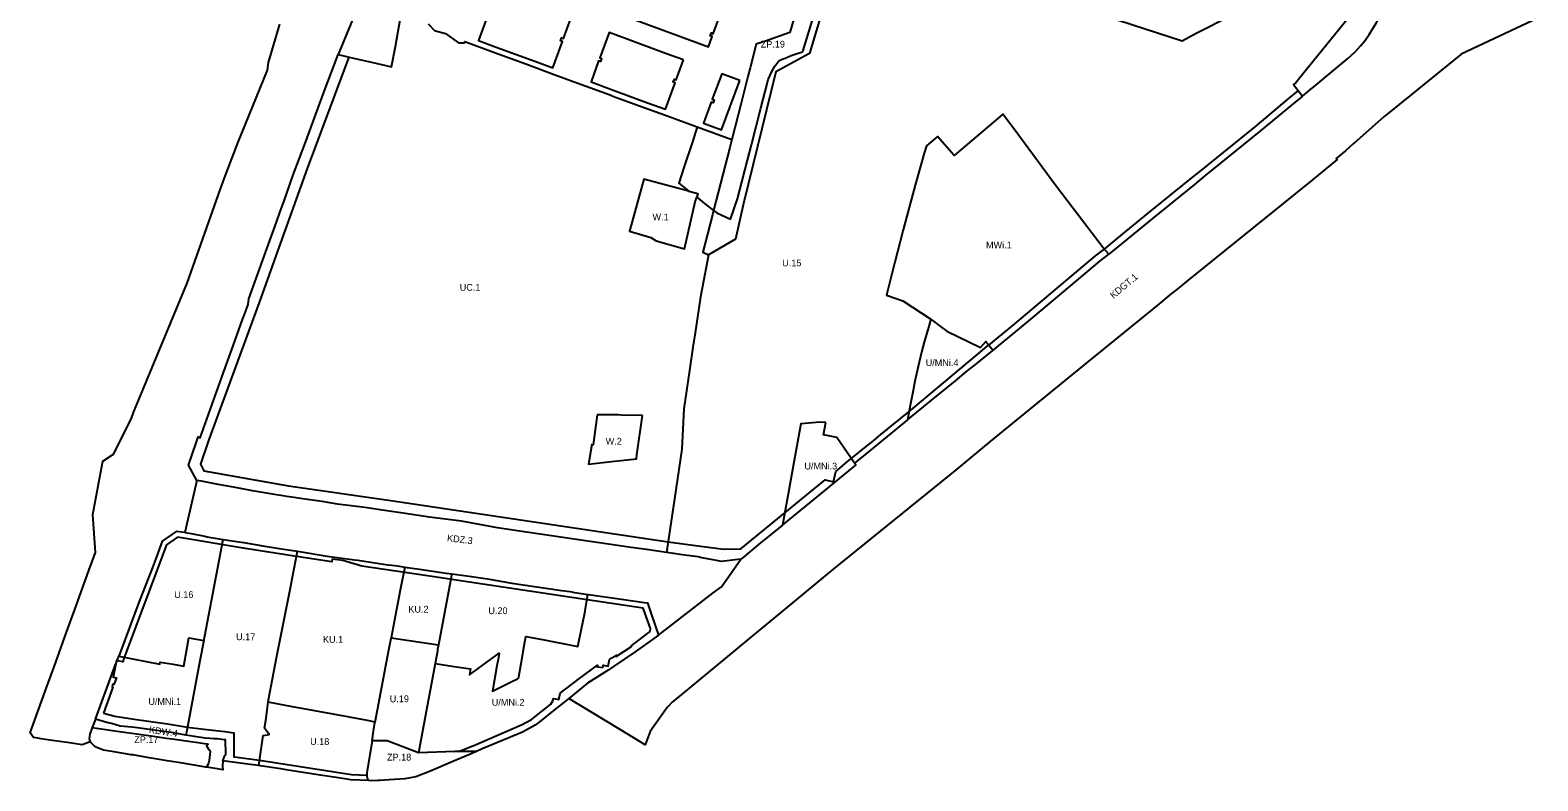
# Model space of a CAD drawing. Extents: x 7428689 to 7430424, y 5549101 to 5550539.
# Drawn here: x 7429291 to 7430402, y 5549101 to 5549654 of the extents above; entities that cross this region are included whole.
import ezdxf

# ---------------------------------------------------------------- set-up
doc = ezdxf.new("R2010")
doc.units = 0
for name, color, linetype in [('linie rozgraniczające', 7, 'Continuous'), ('nieprzekraczalne linie zabudowy', 7, 'Continuous'), ('obowiazujace linie zabudowy', 7, 'Continuous'), ('przeznaczenia terenów', 7, 'Continuous')]:
    doc.layers.add(name, color=color, linetype=linetype)

msp = doc.modelspace()

# ---------------------------------------------------------------- linework, layer by layer
at = {"layer": 'linie rozgraniczające'}
for points in [[(7430228.8, 5549605.5), (7430233.5, 5549609.5), (7430238.8, 5549613.8), (7430249.4, 5549622.6), (7430262.2, 5549633.2), (7430267.9, 5549638.5), (7430271.7, 5549642.7), (7430274.9, 5549646.3), (7430278.1, 5549651.1), (7430283.2, 5549659.4), (7430306.2, 5549703.6), (7430310, 5549710.9), (7430318.2, 5549726.4), (7430322.5, 5549734.6), (7430323, 5549735.8), (7430324.7, 5549739.9), (7430326.1, 5549745.2), (7430327.1, 5549750.3), (7430327.2, 5549753.5), (7430326.6, 5549756.8), (7430324.7, 5549761.7), (7430322.9, 5549765.9), (7430319.8, 5549769.8)], [(7429568.6, 5549761.1), (7429566.9, 5549757.4), (7429563.8, 5549750.5), (7429557, 5549735.5), (7429550.5, 5549716.1), (7429548.8, 5549710.9), (7429543.4, 5549697.4), (7429542.4, 5549694.9), (7429541.4, 5549692.4), (7429533.8, 5549674.3), (7429517.9, 5549636.2)], [(7429874.9, 5549734.7), (7429871, 5549721.6), (7429867.1, 5549708.1), (7429860.8, 5549686.4), (7429850.9, 5549652.5), (7429833, 5549646.2), (7429826.1, 5549643.8), (7429821.7, 5549626.5), (7429820.1, 5549620.2), (7429815, 5549600.4), (7429808.2, 5549573.6), (7429806.7, 5549567.7), (7429794.7, 5549521.4)], [(7429794.7, 5549521.4), (7429797.1, 5549519.5), (7429807.1, 5549514.9), (7429812.4, 5549529.9), (7429821.2, 5549564), (7429822.7, 5549569.8), (7429829.6, 5549596.7), (7429834.4, 5549615.7), (7429835, 5549617.8), (7429837.9, 5549624.3), (7429839.9, 5549627.8), (7429842.9, 5549631.6), (7429845.4, 5549632.8), (7429847.4, 5549633.7), (7429852, 5549635.5), (7429857.8, 5549637.4), (7429859.9, 5549638.1), (7429860.9, 5549639.3), (7429874.1, 5549682.9), (7429888.8, 5549731.4), (7429889.3, 5549732.8)], [(7430278.8, 5549683.1), (7430236.2, 5549630.6), (7430233.1, 5549626.7), (7430232.9, 5549626.4), (7430223.9, 5549615.4), (7430222.3, 5549614.1), (7430228.8, 5549605.5)], [(7429517.9, 5549636.2), (7429530.2, 5549633.4), (7429542.6, 5549630.6), (7429557.3, 5549627.3), (7429560.2, 5549642.3), (7429564, 5549663.2)], [(7430402.4, 5549663.1), (7430346, 5549636.5), (7430345.7, 5549636.3), (7430336.5, 5549628.9), (7430295, 5549595.3), (7430289.1, 5549590.5), (7430266.7, 5549570.7), (7430266.6, 5549570.7), (7430260.5, 5549565.4), (7430253.8, 5549559.6), (7430254.6, 5549558.8), (7430236.2, 5549544), (7430186.6, 5549503.9), (7430143.4, 5549469.1), (7430136.2, 5549463.2), (7430132.4, 5549460.2), (7430121.7, 5549451.4), (7430078.6, 5549416.3), (7430056.2, 5549398.1), (7429999, 5549351.4), (7429974, 5549330.6), (7429882.8, 5549257.1), (7429848.7, 5549228.9), (7429820.8, 5549205.8), (7429803.5, 5549191.5), (7429777.9, 5549170.4), (7429765.5, 5549160.1), (7429764.5, 5549159.3), (7429760.8, 5549155.3), (7429759.4, 5549153.3), (7429748.1, 5549137.3)], [(7429335, 5549129.9), (7429329.3, 5549127.6), (7429319.8, 5549129), (7429305.4, 5549131.1), (7429299, 5549132.1), (7429296.6, 5549132.4), (7429293.3, 5549132.9), (7429290.9, 5549136.3), (7429302.7, 5549169), (7429307.8, 5549183.1), (7429308.5, 5549185), (7429317.7, 5549210.5), (7429323.8, 5549227.2), (7429334.2, 5549256.1), (7429339, 5549269.2), (7429337, 5549297.4), (7429344.5, 5549336.6), (7429352.2, 5549341.7), (7429364.3, 5549365.5), (7429365.5, 5549368.3), (7429367.1, 5549372.4), (7429394.7, 5549438.7), (7429406.7, 5549467.7), (7429431.2, 5549537.2), (7429433.8, 5549544.7), (7429435.4, 5549548.7), (7429444.3, 5549571.6), (7429465.9, 5549624.8), (7429466.6, 5549630.4), (7429474.9, 5549658.6)], [(7429584.3, 5549658.9), (7429589.1, 5549654), (7429597.1, 5549651.7), (7429606.6, 5549644.9), (7429611, 5549644.9), (7429611.4, 5549645.8), (7429633.2, 5549637.8), (7429656.2, 5549629.4), (7429677.2, 5549621.6), (7429697.4, 5549614.2), (7429718.6, 5549606.5), (7429720.5, 5549605.7), (7429739.5, 5549598.8), (7429761.2, 5549590.8), (7429782.7, 5549582.9), (7429779.3, 5549572), (7429772.9, 5549553), (7429769.2, 5549541.5), (7429776.4, 5549535.6)], [(7429413.8, 5549322.4), (7429407.7, 5549333.6), (7429413.3, 5549350.1), (7429414.8, 5549354.5), (7429416.1, 5549353.9), (7429433.4, 5549401.9), (7429440.6, 5549421.7), (7429447.5, 5549440.9), (7429448.9, 5549444.8), (7429451.5, 5549452.1), (7429452.1, 5549456.3), (7429462.2, 5549484.3), (7429467.6, 5549499.2), (7429472.5, 5549512.7), (7429475.2, 5549520.5), (7429478, 5549527.7), (7429484.9, 5549547.5), (7429494.1, 5549572.3), (7429506.9, 5549607), (7429517.9, 5549636.2)], [(7430228.8, 5549605.5), (7430228.6, 5549605.4), (7430222.4, 5549600.3), (7430197, 5549579.2), (7430157.2, 5549547.1), (7430149.3, 5549540.6), (7430118.3, 5549515.5), (7430099.4, 5549500), (7430086.2, 5549489.1)], [(7430086.2, 5549489.1), (7430081.9, 5549493.9), (7430059.1, 5549523.7), (7430047.2, 5549539.3), (7430016.3, 5549581.3), (7430008.1, 5549592.4), (7430001.3, 5549586.6), (7429972, 5549561.8), (7429959.9, 5549575.9), (7429958.1, 5549574.3), (7429951.7, 5549569), (7429950, 5549563.5), (7429943.3, 5549539.9), (7429934.6, 5549507), (7429926.1, 5549474.6), (7429922.2, 5549458.9), (7429934.2, 5549454.7), (7429955, 5549441.2)], [(7429776.4, 5549535.6), (7429763.5, 5549539.1), (7429743.3, 5549544.5), (7429732.8, 5549506), (7429748.5, 5549501.4), (7429752.4, 5549499), (7429773.4, 5549493), (7429781.1, 5549527.6), (7429782.3, 5549531.2)], [(7429776.4, 5549535.6), (7429783.1, 5549533.8), (7429782.3, 5549531.2)], [(7429782.3, 5549531.2), (7429788.1, 5549526.6), (7429794.7, 5549521.4)], [(7429794.7, 5549521.4), (7429793.9, 5549518.1), (7429786.8, 5549490.6), (7429791.1, 5549488.6), (7429791.1, 5549488.6), (7429790.6, 5549485.9), (7429785.1, 5549457.8), (7429784.8, 5549455.9), (7429781.1, 5549431.1), (7429779.5, 5549420.5), (7429776.9, 5549403.5), (7429772.7, 5549375.2), (7429771.4, 5549345.5), (7429765.9, 5549308.9), (7429760, 5549269.3)], [(7430000.6, 5549418.2), (7430020.1, 5549434.1), (7430030.1, 5549442.4), (7430057.6, 5549465.6), (7430079.5, 5549484), (7430085.9, 5549488.9), (7430086.2, 5549489.1)], [(7429955, 5549441.2), (7429953.2, 5549435.2), (7429950.1, 5549424.4), (7429948, 5549416.9), (7429945.6, 5549406.3), (7429943.2, 5549395.6), (7429941.8, 5549388.7), (7429939.7, 5549377.7), (7429937.6, 5549367)], [(7429955, 5549441.2), (7429962.1, 5549435.9), (7429966.8, 5549432.5), (7429991.5, 5549420.4), (7429995.5, 5549424.7), (7430000.4, 5549418.8), (7430000.6, 5549418.2)], [(7429937.6, 5549367), (7429955.2, 5549381.3), (7429973, 5549395.8), (7429981.3, 5549402.6), (7429987.7, 5549407.7), (7430000.6, 5549418.2)], [(7429709, 5549370.8), (7429705.9, 5549348.7), (7429704.9, 5549349), (7429702.4, 5549334.4), (7429719.4, 5549336.3), (7429737.8, 5549338.4), (7429738.2, 5549341.3), (7429742.3, 5549370.3)], [(7429742.3, 5549370.3), (7429726.9, 5549370.5), (7429724.4, 5549370.8), (7429709, 5549370.8)], [(7429877.4, 5549365.2), (7429873.4, 5549365.3), (7429859.1, 5549364.1), (7429859.1, 5549364.1), (7429854.2, 5549337.2), (7429849.5, 5549311), (7429845.6, 5549289.5)], [(7429898.6, 5549335.2), (7429891, 5549346.1), (7429885.5, 5549354), (7429875.7, 5549355.9), (7429877.4, 5549365.2)], [(7429937.6, 5549367), (7429907.7, 5549342.6), (7429900, 5549336.3), (7429898.6, 5549335.2)], [(7429845.6, 5549289.5), (7429876.5, 5549314.7), (7429897.2, 5549331.6), (7429899.7, 5549333.6), (7429898.6, 5549335.2)], [(7429413.8, 5549322.4), (7429404.8, 5549284.1)], [(7429760, 5549269.3), (7429750.3, 5549270.7), (7429745.6, 5549271.4), (7429745.2, 5549271.4), (7429733.9, 5549273.1), (7429708.9, 5549276.7), (7429688.6, 5549279.7), (7429670.3, 5549282.3), (7429653.4, 5549284.9), (7429635.5, 5549287.6), (7429608.9, 5549292.4), (7429585.2, 5549295.4), (7429564.1, 5549298.5), (7429555.6, 5549299.8), (7429537.7, 5549302.4), (7429517.4, 5549305), (7429506.2, 5549307), (7429495.4, 5549308.3), (7429480.2, 5549310.5), (7429469.5, 5549312.2), (7429454.7, 5549314.8), (7429444.8, 5549316.6), (7429440.7, 5549317.4), (7429429.6, 5549319.4), (7429417.2, 5549321.8), (7429413.8, 5549322.4)], [(7429845.6, 5549289.5), (7429827.9, 5549275.1), (7429816.7, 5549265.9), (7429814.9, 5549264.5)], [(7429404.8, 5549284.1), (7429398.6, 5549284.8), (7429388.1, 5549277.6), (7429383.9, 5549266.2), (7429381, 5549258.3), (7429371.3, 5549233.2), (7429356.3, 5549192.8)], [(7429404.8, 5549284.1), (7429409.6, 5549283.2), (7429419.6, 5549281.4), (7429421.3, 5549280.9), (7429433.1, 5549279)], [(7429418.9, 5549204.4), (7429419.6, 5549207.9), (7429433.1, 5549279)], [(7429433.1, 5549279), (7429446.4, 5549276.9), (7429448.4, 5549276.6), (7429462.4, 5549274.2), (7429473, 5549272.5), (7429482.9, 5549271.1), (7429487.9, 5549270.4)], [(7429466.4, 5549158.9), (7429466.7, 5549160.8), (7429472.6, 5549191.7), (7429482.5, 5549242.1), (7429484.2, 5549251.2), (7429487.9, 5549270.4)], [(7429487.9, 5549270.4), (7429509.9, 5549266.6), (7429530, 5549263.9), (7429532.5, 5549263.6)], [(7429532.5, 5549263.6), (7429548.1, 5549261.2), (7429554.6, 5549260.3), (7429557.6, 5549259.9), (7429561.6, 5549259.4), (7429567, 5549258.6)], [(7429754.2, 5549208.3), (7429794.5, 5549239.5), (7429800.6, 5549244.1), (7429814.9, 5549264.5)], [(7429814.9, 5549264.5), (7429800.5, 5549262.7), (7429796.9, 5549263.4), (7429784.8, 5549265.7), (7429784.8, 5549265.8), (7429779.8, 5549266.5), (7429775.2, 5549267.2), (7429770.2, 5549267.9), (7429770, 5549267.9), (7429769.9, 5549267.9), (7429765.4, 5549268.6), (7429765, 5549268.6), (7429760.2, 5549269.3), (7429760, 5549269.3)], [(7429567, 5549258.6), (7429563.7, 5549241.5), (7429559.3, 5549218.3), (7429557, 5549206.5)], [(7429567, 5549258.6), (7429577.8, 5549257.1), (7429597.6, 5549254.2), (7429601.7, 5549253.7)], [(7429601.7, 5549253.7), (7429591.9, 5549201.2)], [(7429601.7, 5549253.7), (7429612.7, 5549252.1), (7429628, 5549249.8), (7429646.1, 5549246.8), (7429662.7, 5549244.3), (7429681.1, 5549241.5), (7429682.7, 5549241.3), (7429685, 5549241.1), (7429690.4, 5549240.4), (7429690.8, 5549240.1), (7429702.1, 5549238.4)], [(7429589.4, 5549187.5), (7429603.5, 5549185.4), (7429615.5, 5549183.5), (7429614.7, 5549179.1), (7429631.3, 5549191.2), (7429636.7, 5549195.1), (7429635.9, 5549190.4), (7429635, 5549185.7), (7429631.7, 5549167.1), (7429645.9, 5549174.2), (7429645.9, 5549174.2), (7429650.1, 5549176.2), (7429651, 5549176.7), (7429651.2, 5549177.7), (7429652.8, 5549187.6), (7429655.3, 5549201.9), (7429656.2, 5549207.3), (7429668.7, 5549205.1), (7429694.7, 5549200), (7429699.7, 5549224.9), (7429702.1, 5549238.4)], [(7429702.1, 5549238.4), (7429702.4, 5549238.4), (7429726.8, 5549234.8), (7429743.5, 5549232.4), (7429745.9, 5549232.1), (7429748.9, 5549223.4), (7429754.2, 5549208.3)], [(7429754.2, 5549208.3), (7429746.3, 5549202.8), (7429740.3, 5549198.6), (7429736.8, 5549196.2), (7429721, 5549185.2), (7429717, 5549182.6), (7429701.7, 5549173.1), (7429687.9, 5549161.8)], [(7429356.3, 5549192.8), (7429386.5, 5549187.1), (7429386.8, 5549188.4), (7429396.2, 5549186.9), (7429404.2, 5549185.5), (7429407.9, 5549206.4), (7429418.9, 5549204.4)], [(7429418.9, 5549204.4), (7429416, 5549189.4), (7429406.3, 5549138.1), (7429405.7, 5549134.8)], [(7429545.2, 5549144.4), (7429555.3, 5549197.7), (7429557, 5549206.3), (7429557.1, 5549206.3), (7429557, 5549206.5)], [(7429557, 5549206.5), (7429591.9, 5549201.2)], [(7429591.9, 5549201.2), (7429591.9, 5549201.1), (7429591.3, 5549198), (7429591.3, 5549198), (7429591.1, 5549196.5), (7429589.4, 5549187.5)], [(7429339, 5549146.4), (7429340.1, 5549149.3), (7429353.7, 5549186.8), (7429354.1, 5549186.9), (7429356.3, 5549192.8)], [(7429589.4, 5549187.5), (7429581.6, 5549145.5), (7429577.2, 5549121.7)], [(7429459.4, 5549112.3), (7429462.7, 5549134.5), (7429467.2, 5549135.1), (7429465.2, 5549137.8), (7429463.7, 5549139.8), (7429464.7, 5549145.5), (7429466.4, 5549158.9)], [(7429545.2, 5549144.4), (7429539.7, 5549145.4), (7429526.4, 5549147.9), (7429508.9, 5549151.1), (7429488.5, 5549154.8), (7429484.4, 5549155.6), (7429466.4, 5549158.9)], [(7429687.9, 5549161.8), (7429677.8, 5549153.6), (7429666.2, 5549144.4), (7429663.2, 5549142.1), (7429653.9, 5549136.9), (7429643.9, 5549132.7), (7429624, 5549124.6), (7429619.9, 5549122.6)], [(7429748.1, 5549137.3), (7429744.4, 5549127.5), (7429739.9, 5549130.4), (7429731, 5549135.8), (7429726.7, 5549138.3), (7429714.8, 5549145.5), (7429694.9, 5549157.5), (7429687.9, 5549161.8)], [(7429339, 5549146.4), (7429336.7, 5549140.3)], [(7429405.7, 5549134.8), (7429396.6, 5549136.3), (7429383.9, 5549138.2), (7429371.8, 5549139.9), (7429365.9, 5549140.7), (7429357.3, 5549141.3), (7429350.9, 5549143.2), (7429348.3, 5549143.9), (7429345.6, 5549144.6), (7429339, 5549146.4)], [(7429542.9, 5549130.5), (7429544.1, 5549137.7), (7429545.1, 5549144), (7429545.2, 5549144.4)], [(7429336.7, 5549140.3), (7429334.9, 5549135.4), (7429334.5, 5549132.1), (7429335, 5549129.9)], [(7429420.4, 5549111.2), (7429401.8, 5549114.3), (7429391.9, 5549115.9), (7429378.5, 5549118.1), (7429366.6, 5549120.1), (7429365.1, 5549120.3), (7429361.5, 5549120.9), (7429361.1, 5549121), (7429352.6, 5549122.4), (7429345, 5549123.6), (7429338.9, 5549126), (7429335, 5549129.9)], [(7429336.7, 5549140.3), (7429339.9, 5549139.8), (7429358.5, 5549137.2), (7429369.4, 5549135.6), (7429372.6, 5549135.2), (7429380.1, 5549134.1), (7429391.5, 5549132.6), (7429397.3, 5549131.8), (7429407.6, 5549130.4), (7429414.8, 5549129.3), (7429419.5, 5549128.6), (7429421.4, 5549128.3), (7429422, 5549128.1), (7429420.8, 5549126.9), (7429422.2, 5549124.9), (7429423.2, 5549123.7), (7429423.5, 5549122.7), (7429423.6, 5549122.1), (7429423.4, 5549120.4)], [(7429432.9, 5549115.9), (7429434.5, 5549119.8), (7429435.2, 5549120.6), (7429435, 5549131.3), (7429433.8, 5549131.3), (7429428.7, 5549131.9), (7429426.3, 5549132.1), (7429423.5, 5549132.2), (7429419.9, 5549132.5), (7429412.1, 5549133.7), (7429405.7, 5549134.8)], [(7429542.9, 5549130.5), (7429539.4, 5549108.7), (7429539.2, 5549106.7), (7429539.2, 5549104.6), (7429539.6, 5549102.6), (7429540, 5549101.2)], [(7429577.2, 5549121.7), (7429554.1, 5549130.6), (7429551.5, 5549130.6), (7429542.9, 5549130.5)], [(7429423.4, 5549120.4), (7429422.9, 5549116.1), (7429422.4, 5549114.1), (7429422.1, 5549113.3), (7429421.4, 5549112.2), (7429420.4, 5549111.2)], [(7429619.9, 5549122.6), (7429614.4, 5549120.3), (7429602.4, 5549115.4), (7429586.5, 5549108.4), (7429575.1, 5549103.9), (7429567, 5549102.5), (7429555.6, 5549101.8), (7429548.6, 5549101.4), (7429547.1, 5549101.3), (7429542.6, 5549101.1), (7429540, 5549101.2)], [(7429619.9, 5549122.6), (7429604, 5549122.6), (7429577.2, 5549121.7)], [(7429432.9, 5549115.9), (7429432.6, 5549111.9), (7429433, 5549109.2), (7429429, 5549109.8), (7429428.8, 5549109.9), (7429421.1, 5549111.1), (7429420.4, 5549111.2)], [(7429459.4, 5549112.3), (7429453.1, 5549113.2), (7429432.9, 5549115.9)], [(7429540, 5549101.2), (7429527.4, 5549101.7), (7429518.1, 5549103.2), (7429504.7, 5549105.2), (7429500.1, 5549105.9), (7429479.6, 5549109.2), (7429475.6, 5549109.8), (7429460.4, 5549112.2), (7429459.4, 5549112.3)]]:
    msp.add_lwpolyline(points, dxfattribs=at)
at = {"layer": 'nieprzekraczalne linie zabudowy'}
msp.add_line((7429782.7, 5549582.9), (7429808.2, 5549573.6), dxfattribs=at)
for points in [[(7430250.8, 5549741.6), (7430250.2, 5549740.8), (7430211.4, 5549693.5), (7430176.3, 5549664.7), (7430150.6, 5549651.8), (7430140.1, 5549646), (7430038, 5549679.6), (7430014.8, 5549688), (7429975.2, 5549702.2), (7429941.9, 5549714.2), (7429926.2, 5549719.8), (7429897.5, 5549723.6), (7429891.4, 5549724.3), (7429865.5, 5549637), (7429840.6, 5549623.4), (7429816.8, 5549526.6), (7429810.8, 5549500.3)], [(7429525.8, 5549634.4), (7429525.3, 5549633.2), (7429495.2, 5549552.4), (7429474.3, 5549494), (7429459.6, 5549453.5), (7429422.3, 5549351.8), (7429416.4, 5549334.3), (7429419, 5549329.6), (7429481.4, 5549318.4), (7429556.7, 5549307.7), (7429761.2, 5549277.2), (7429785, 5549274), (7429802.2, 5549271.7), (7429814.9, 5549272.1), (7429877, 5549322.8), (7429883.2, 5549321.5), (7429884.8, 5549329.1), (7429893.2, 5549336), (7429909.6, 5549349.4), (7429911.3, 5549350.7), (7429918.4, 5549356.6), (7429920.5, 5549358.3), (7429925.9, 5549362.7), (7429938.8, 5549373)], [(7429997.6, 5549422.2), (7430016.9, 5549437.9), (7430054.4, 5549469.4), (7430076.4, 5549487.9), (7430083.1, 5549493), (7430096.3, 5549503.9), (7430115.1, 5549519.4), (7430146.1, 5549544.5), (7430154.1, 5549550.9), (7430193.9, 5549583.1), (7430219.2, 5549604.1), (7430225.7, 5549609.5)], [(7429810.8, 5549500.3), (7429791.1, 5549488.6)], [(7429938.6, 5549372.9), (7429997.4, 5549422), (7429997.6, 5549422.2)], [(7429997.6, 5549422.2), (7429997.6, 5549422.2)], [(7429701.5, 5549234.4), (7429577.2, 5549253.1), (7429535.3, 5549259.3), (7429521.3, 5549263.5), (7429513.5, 5549264.3), (7429513.4, 5549262.5), (7429487.3, 5549266.4), (7429447.8, 5549272.6), (7429399.5, 5549280.6), (7429391.4, 5549275), (7429360.3, 5549192)], [(7429748, 5549211.2), (7429748.2, 5549213.3), (7429742.9, 5549228.4), (7429701.5, 5549234.4)], [(7429606.6, 5549122.6), (7429617.3, 5549126.9), (7429617.9, 5549127.2), (7429653.5, 5549142.5), (7429660.4, 5549146.3), (7429674.7, 5549157.5), (7429676.3, 5549160.1), (7429676.6, 5549161.8), (7429680.7, 5549161), (7429681.6, 5549165.6), (7429696.2, 5549176.6), (7429709.1, 5549186.3), (7429708.9, 5549185.1), (7429709.3, 5549185.1), (7429713.1, 5549184.5), (7429713.4, 5549186.2), (7429717.1, 5549185.5), (7429718.1, 5549190.5), (7429719.8, 5549191.6), (7429723.1, 5549193.6), (7429722.9, 5549192.6), (7429734.2, 5549200.1), (7429734.4, 5549200.8), (7429735.7, 5549201.7), (7429748, 5549211.2)], [(7429360.3, 5549192), (7429360, 5549191.3), (7429359.1, 5549188.8), (7429354.5, 5549189.7), (7429352.1, 5549177.5), (7429354.5, 5549177), (7429352.6, 5549172), (7429351.5, 5549172.1), (7429351.3, 5549170.1), (7429351.9, 5549170), (7429344.9, 5549151)], [(7429344.9, 5549151), (7429353.2, 5549148.7), (7429367.6, 5549146.5), (7429392.2, 5549143), (7429406.8, 5549140.6), (7429418.9, 5549139.2), (7429427.7, 5549138.1), (7429434.3, 5549137.3), (7429441.1, 5549136.5), (7429441.1, 5549127.1), (7429441, 5549122.1), (7429441, 5549118.8), (7429441.5, 5549118.7), (7429459.9, 5549116.3), (7429527.8, 5549105.7), (7429539.2, 5549105.2)]]:
    msp.add_lwpolyline(points, dxfattribs=at)
at = {"layer": 'obowiazujace linie zabudowy'}
for points in [[(7429634.7, 5549683), (7429627.8, 5549664.3), (7429629.2, 5549663.8), (7429628.4, 5549661.6), (7429627, 5549662.1), (7429621.3, 5549646.6), (7429634.5, 5549641.7), (7429663, 5549631.3), (7429676.2, 5549626.4), (7429683.3, 5549645.8), (7429681.9, 5549646.4), (7429682.7, 5549648.5), (7429684.1, 5549648), (7429689.5, 5549662.8), (7429676.3, 5549667.6), (7429648, 5549678.1), (7429634.7, 5549683)], [(7429772.6, 5549632.3), (7429759.3, 5549637.1), (7429731, 5549647.6), (7429717.7, 5549652.4), (7429710.8, 5549633.8), (7429712.2, 5549633.3), (7429711.4, 5549631.1), (7429710, 5549631.6), (7429704.5, 5549616.1), (7429717.6, 5549611.2), (7429745.9, 5549600.7), (7429759.2, 5549596), (7429766.3, 5549615.3), (7429764.9, 5549615.8), (7429765.8, 5549618.1), (7429767.2, 5549617.5), (7429772.6, 5549632.3)], [(7429814, 5549617.1), (7429800.7, 5549622), (7429793.8, 5549603.3), (7429795.2, 5549602.8), (7429794.4, 5549600.7), (7429793, 5549601.2), (7429787.3, 5549585.6), (7429800.6, 5549580.7), (7429814, 5549617.1)]]:
    msp.add_lwpolyline(points, dxfattribs=at)
msp.add_lwpolyline([(7429736.8, 5549661.9), (7429791, 5549641.9), (7429793.7, 5549649.5), (7429792.3, 5549650), (7429793.2, 5549652.2), (7429794.5, 5549651.6), (7429799.4, 5549664.7), (7429745.2, 5549684.6), (7429740.3, 5549671.5), (7429741.7, 5549671), (7429741, 5549668.9), (7429739.6, 5549669.4)], close=True, dxfattribs=at)

# ---------------------------------------------------------------- texts
at = {"layer": 'przeznaczenia terenów'}
for s, p in [('ZP.19', (7429829.5, 5549641.4)), ('W.1', (7429749.7, 5549514.1)), ('MWi.1', (7429995.6, 5549493.4)), ('U.15', (7429845.3, 5549480.2)), ('UC.1', (7429607.6, 5549462.2)), ('U/MNi.4', (7429951.1, 5549406.7)), ('W.2', (7429715.2, 5549348.8)), ('U/MNi.3', (7429861.7, 5549330.5)), ('U.16', (7429397.1, 5549235.8)), ('KU.2', (7429569.7, 5549225)), ('U.20', (7429628.7, 5549223.9)), ('U.17', (7429442.7, 5549204.7)), ('KU.1', (7429506.8, 5549202.8)), ('U.19', (7429556, 5549159)), ('U/MNi.1', (7429378, 5549157)), ('U/MNi.2', (7429631.2, 5549156.4)), ('ZP.17', (7429367.6, 5549128.9)), ('U.18', (7429497.3, 5549127.5)), ('ZP.18', (7429554, 5549116))]:
    msp.add_text(s, height=5, dxfattribs=at).set_placement(p)
for s, rotation, p in [('KDGT.1', 40.0819, (7430089.6, 5549456.1)), ('KDZ.3', 352.8314, (7429598, 5549277.7)), ('KDW.4', 351.6505, (7429378.3, 5549136.4))]:
    msp.add_text(s, height=5, rotation=rotation, dxfattribs=at).set_placement(p)

doc.saveas('drawing.dxf')
